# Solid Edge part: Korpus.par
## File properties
Author: Türk
Template: Iso Part.par
Last saved by: Türk
Revision: 9
Application: Solid Edge
Accuracy: 0,990
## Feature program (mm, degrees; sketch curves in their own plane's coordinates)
thread "unnamed Thread 1"
thread "unnamed Thread 2"
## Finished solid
Body 1: solid body, 43 faces, 98 edges, 54 vertices.
  Faces by surface: plane 27, cylinder 16
  Edges by curve: line 64, circle 32, intersection 2
Bounding box of the edges (mm): 140.000 x 61.000 x 100.000, from (-70, -51, -50) to (70, 10, 50).
Cylindrical faces by radius (mm): R3.7295 x2, R6 x3, R7.5 x3, R15 x2, R16 x2, R19 x2, R20 x2
Planar faces by outward normal: +x 5, +y 1, +z 3, -x 5, -y 8, -z 5
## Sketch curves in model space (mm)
circle centre (-32.8634, 0, 3) radius 13
circle centre (0, 0, 20) radius 13
circle centre (50, 0, 30) radius 4
circle centre (-50, 0, 30) radius 4
circle centre (-32.8634, 0, 3) radius 26
circle centre (0, 0, -14) radius 26
arc centre (50, 0, 30) radius 20 from (50, 0, 50) through (64.5475, 0, 43.7248) to (70, 0, 30)
line (70, 0, 30) -> (70, 0, -50)
line (70, 0, -50) -> (-70, 0, -50)
line (-70, 0, -50) -> (-70, 0, 30)
arc centre (-50, 0, 30) radius 20 from (-50, 0, 50) through (-64.5475, 0, 43.7248) to (-70, 0, 30)
line (-50, 0, 50) -> (50, 0, 50)
arc centre (50, 0, 30) radius 17.5 from (50, 0, 47.5) through (62.729, 0, 42.0092) to (67.5, 0, 30)
line (67.5, 0, 30) -> (67.5, 0, -47.5)
line (67.5, 0, -47.5) -> (-67.5, 0, -47.5)
line (-67.5, 0, -47.5) -> (-67.5, 0, 30)
arc centre (-50, 0, 30) radius 17.5 from (-67.5, 0, 30) through (-62.0092, 0, 42.729) to (-50, 0, 47.5)
line (-50, 0, 47.5) -> (50, 0, 47.5)
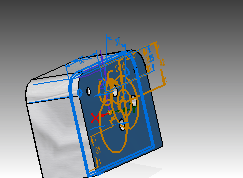
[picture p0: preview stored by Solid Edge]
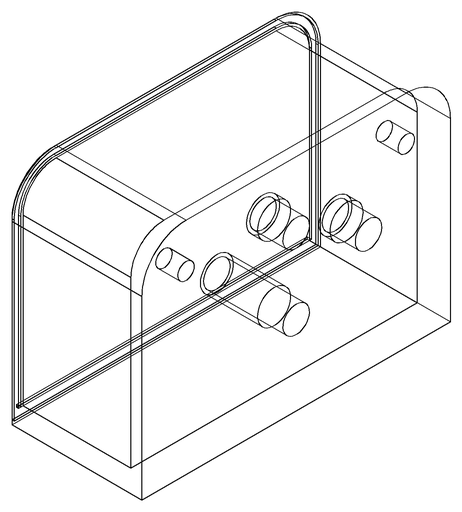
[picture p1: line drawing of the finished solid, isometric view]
